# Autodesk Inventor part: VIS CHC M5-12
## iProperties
Created: 2004-11
Part Number: VIS CHC M5-12
Document SubType Name: Modeling
Designer: Bruno
Manufacturer: Standard
Standards Organization: Custom
Author: Bruno
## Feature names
1. Base1
